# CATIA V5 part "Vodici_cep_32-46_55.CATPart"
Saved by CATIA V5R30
Part number: Vodici_cep_32-46_55
Definition: E 1000_32-46_55_2
Nomenclature: E 1000_32-46_55_2
Source: Unknown
Description: PART--DESC
Bounding box of the stored display mesh (mm): x -210.3 to -163.7, y -160.3 to -113.7, z -101 to 9
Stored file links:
  E:\Bakalarka\Model\Forma_v7\Vodici_cep_32-46_55.CATPart
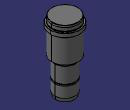
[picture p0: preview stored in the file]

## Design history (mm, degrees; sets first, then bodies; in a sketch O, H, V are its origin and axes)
Body1 "MANIFOLD_SOLID_BREP #3946" (main body)
  Solid1: solid without history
